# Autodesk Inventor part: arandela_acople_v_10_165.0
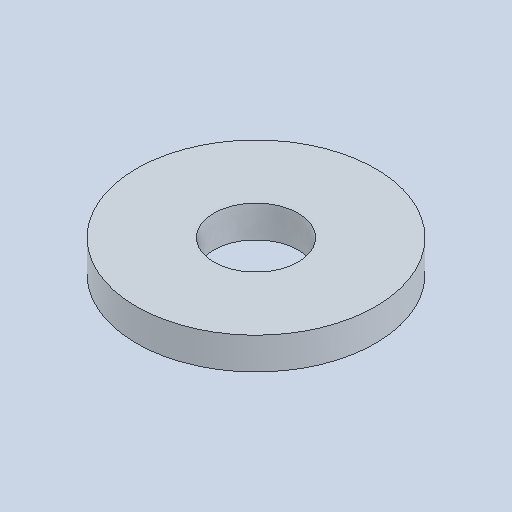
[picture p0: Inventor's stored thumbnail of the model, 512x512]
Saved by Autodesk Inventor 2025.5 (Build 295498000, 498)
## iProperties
Created: 2026-10
Part Number: arandela_acople_v_10_165.0
Material: Genérico
Document SubType Name: Modeling
Designer: Luis M
Density: 1 g/cm^3
Appearance: Valor por defecto
Author: Luis M
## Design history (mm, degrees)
feature "Base1"
node "Sólido1"
